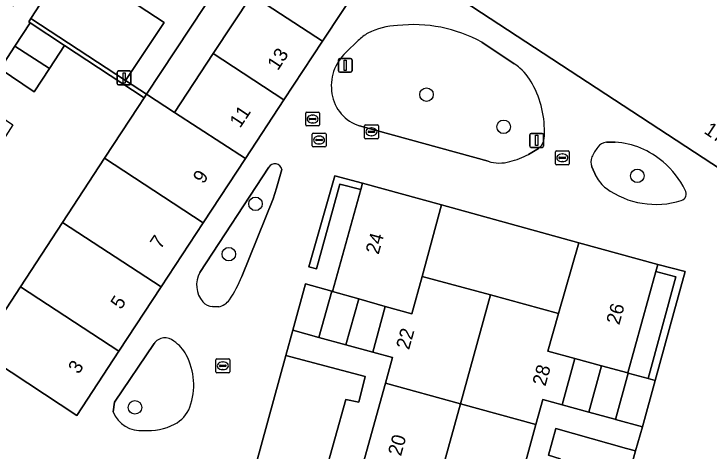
# Model space of a CAD drawing. Extents: x 159279 to 160377, y 384531 to 385888.
# Drawn here: x 159687.1 to 159737.3, y 385007.8 to 385039.4 of the extents above; entities that cross this region are included whole.
import ezdxf

# ---------------------------------------------------------------- set-up
doc = ezdxf.new("R2010")
doc.units = 0
for name, color, linetype in [('IMGEO_Boom', 7, 'Continuous'), ('IMGEO_Erf', 7, 'Continuous'), ('IMGEO_Groenvoorziening', 7, 'Continuous'), ('IMGEO_Hek', 7, 'Continuous'), ('IMGEO_Kolk', 7, 'Continuous'), ('IMGEO_Lichtmast', 7, 'Continuous'), ('IMGEO_Pand', 7, 'Continuous'), ('IMGEO_Pand_nummerreeks', 7, 'Continuous'), ('IMGEO_Parkeervlak_open', 7, 'Continuous'), ('IMGEO_Rijbaan_lokaal_open', 7, 'Continuous'), ('IMGEO_Rioolput', 7, 'Continuous'), ('IMGEO_Voetpad_open', 7, 'Continuous')]:
    doc.layers.add(name, color=color, linetype=linetype)

msp = doc.modelspace()

# ---------------------------------------------------------------- linework, layer by layer
at = {"layer": 'IMGEO_Boom'}
for centre in [(159716.879, 385033.612), (159722.449, 385031.285), (159732.109, 385027.742), (159704.53, 385025.718), (159702.603, 385022.074), (159695.825, 385011.001)]:
    msp.add_circle(centre, 0.489, dxfattribs=at)
at = {"layer": 'IMGEO_Erf'}
for points in [[(159707.037, 385045.044), (159705.037, 385046.345), (159696.664, 385033.634), (159698.671, 385032.329), (159701.473, 385036.588), (159704.263, 385040.828)], [(159693.635, 385029.02), (159696.07, 385032.741), (159696.49, 385033.372), (159690.738, 385037.169), (159689.648, 385035.49), (159688.557, 385033.812), (159686.092, 385035.477), (159684.54, 385033.097), (159687.007, 385031.43), (159685.921, 385029.756), (159684.836, 385028.082), (159683.75, 385026.408), (159681.278, 385028.08), (159679.412, 385025.221), (159681.889, 385023.564), (159680.81, 385021.913), (159679.708, 385020.226), (159677.219, 385021.881), (159676.297, 385020.469), (159684.516, 385015.086), (159687.554, 385019.728), (159690.594, 385024.374)]]:
    msp.add_lwpolyline(points, close=True, dxfattribs=at)
at = {"layer": 'IMGEO_Groenvoorziening'}
for points in [[(159688.313, 385039.115), (159688.159, 385038.87), (159688.265, 385038.797), (159690.738, 385037.169), (159696.49, 385033.372), (159696.664, 385033.634), (159695.151, 385034.636)], [(159712.135, 385026.744), (159712.264, 385027.21), (159710.255, 385027.738), (159708.395, 385021.161), (159708.936, 385021.015), (159710.631, 385027.136)], [(159727.877, 385022.906), (159717.977, 385025.649), (159716.563, 385020.475), (159721.493, 385019.127), (159726.423, 385017.779)], [(159733.579, 385021.34), (159733.438, 385020.828), (159734.885, 385020.437), (159732.892, 385013.082), (159733.39, 385012.945), (159734.748, 385017.863), (159735.566, 385020.832)], [(159706.728, 385014.756), (159702.407, 384999.024), (159702.463, 384999.012), (159702.875, 384998.904), (159707.309, 384997.745), (159708.147, 384997.525), (159708.628, 384999.364), (159707.709, 384999.604), (159709.052, 385004.403), (159709.273, 385005.211), (159711.651, 385004.56), (159711.749, 385004.916), (159711.833, 385005.22), (159709.458, 385005.886), (159711.051, 385011.567), (159711.984, 385011.373), (159712.446, 385013.228)], [(159731.988, 385007.852), (159731.335, 385008.036), (159726.225, 385009.479), (159725.699, 385007.547), (159726.546, 385007.283), (159725.336, 385002.644), (159725.001, 385001.456), (159722.677, 385002.088), (159722.628, 385001.911), (159722.576, 385001.723), (159724.905, 385001.064), (159723.474, 384995.85), (159723.308, 384995.283), (159723.108, 384995.336), (159722.416, 384995.519), (159721.904, 384993.59), (159727.401, 384992.085), (159727.639, 384992.018)]]:
    msp.add_lwpolyline(points, close=True, dxfattribs=at)
for points in [[(159711.955, 385037.529), (159711.051, 385036.645)], [(159723.208, 385035.834), (159720.868, 385037.407)], [(159712.052, 385031.348), (159721.336, 385028.789)], [(159730.511, 385030.176), (159729.874, 385030.174)], [(159724.255, 385029.29), (159724.964, 385029.723)], [(159705.5, 385028.368), (159700.508, 385020.752)], [(159703.552, 385020.471), (159705.815, 385026.087), (159706.06, 385026.856), (159706.426, 385028.202)], [(159728.831, 385028.381), (159729.145, 385027.684)], [(159701.418, 385018.285), (159701.872, 385018.268)], [(159697.203, 385015.616), (159694.341, 385011.373)], [(159694.341, 385011.373), (159694.249, 385010.673)]]:
    msp.add_lwpolyline(points, dxfattribs=at)
for centre, radius, start, end in [((159714.985, 385033.449), 5.158, 92.2605, 116.8738), ((159715.929, 385028.357), 10.31, 61.3761, 96.3881), ((159714.44, 385034.924), 3.6, 119.7448, 133.6533), ((159713.279, 385034.246), 3.274, 132.8813, 190.1333), ((159722.59, 385034.575), 1.402, 42.2413, 63.8445), ((159720.925, 385032.429), 4.104, 25.0343, 48.8139), ((159718.388, 385030.997), 7.013, 355.266, 26.8654), ((159712.908, 385034.102), 2.884, 188.6226, 252.7424), ((159724.394, 385030.532), 0.99, 305.1831, 353.3756), ((159730.003, 385029.233), 0.95, 97.7841, 142.8195), ((159730.134, 385024.353), 5.835, 48.8814, 86.2934), ((159732.099, 385027.644), 3.581, 142.8282, 155.964), ((159721.487, 385034.535), 5.93, 283.7329, 297.8218), ((159729.601, 385028.744), 0.851, 155.0924, 205.2254), ((159705.931, 385028.108), 0.504, 10.7746, 148.8989), ((159722.14, 385031.339), 2.674, 252.4994, 286.3981), ((159729.814, 385023.859), 6.418, 26.3701, 49.6285), ((159731.395, 385028.857), 2.538, 207.5406, 232.5773), ((159733.448, 385031.782), 6.109, 233.9526, 287.4686), ((159735.133, 385026.44), 0.509, 287.0404, 32.0469), ((159702.14, 385019.85), 1.864, 151.0731, 220.6856), ((159694.881, 385024.007), 9.364, 326.0617, 337.8144), ((159701.496, 385019.298), 1.016, 220.7307, 265.6105), ((159701.579, 385019.562), 1.327, 282.7638, 323.831), ((159697.995, 385015.066), 0.965, 48.0475, 145.2102), ((159697.307, 385013.7), 2.473, 26.2591, 57.388), ((159695.403, 385012.606), 4.666, 340.1761, 27.9563), ((159697.664, 385011.827), 2.275, 296.6333, 339.3357), ((159696.242, 385011.479), 2.149, 202.0248, 275.6203), ((159696.817, 385013.267), 3.944, 264.6911, 298.2544)]:
    msp.add_arc(centre, radius, start, end, dxfattribs=at)
at = {"layer": 'IMGEO_Hek'}
msp.add_lwpolyline([(159707.037, 385045.044), (159705.037, 385046.345), (159696.664, 385033.634)], dxfattribs=at)
at = {"layer": 'IMGEO_Kolk'}
for p, q in [((159712.406, 385030.493), (159712.406, 385031.345)), ((159712.481, 385031.419), (159713.333, 385031.419)), ((159712.894, 385031.199), (159712.919, 385031.199)), ((159713.407, 385031.345), (159713.407, 385030.493)), ((159712.665, 385030.913), (159712.665, 385030.925)), ((159713.103, 385030.876), (159712.705, 385030.876)), ((159712.708, 385030.962), (159713.106, 385030.962)), ((159712.917, 385030.639), (159712.892, 385030.639)), ((159713.149, 385030.925), (159713.149, 385030.913)), ((159713.333, 385030.419), (159712.481, 385030.419)), ((159726.189, 385028.618), (159726.189, 385029.47)), ((159726.264, 385029.544), (159727.116, 385029.544)), ((159726.448, 385029.038), (159726.448, 385029.05)), ((159726.491, 385029.087), (159726.889, 385029.087)), ((159726.677, 385029.324), (159726.702, 385029.324)), ((159726.932, 385029.05), (159726.932, 385029.038)), ((159727.19, 385029.47), (159727.19, 385028.618)), ((159726.886, 385029.001), (159726.488, 385029.001)), ((159726.7, 385028.764), (159726.675, 385028.764)), ((159727.116, 385028.544), (159726.264, 385028.544)), ((159701.747, 385014.51), (159702.599, 385014.51)), ((159701.672, 385013.584), (159701.672, 385014.436)), ((159701.931, 385014.004), (159701.931, 385014.016)), ((159701.974, 385014.053), (159702.372, 385014.053)), ((159702.16, 385014.29), (159702.185, 385014.29)), ((159702.415, 385014.016), (159702.415, 385014.004)), ((159702.673, 385014.436), (159702.673, 385013.584)), ((159702.599, 385013.51), (159701.747, 385013.51)), ((159702.369, 385013.967), (159701.971, 385013.967)), ((159702.183, 385013.73), (159702.158, 385013.73))]:
    msp.add_line(p, q, dxfattribs=at)
for points in [[(159712.406, 385030.493), (159712.406, 385031.345)], [(159712.481, 385031.419), (159713.333, 385031.419)], [(159713.407, 385031.345), (159713.407, 385030.493)], [(159713.333, 385030.419), (159712.481, 385030.419)], [(159726.189, 385028.618), (159726.189, 385029.47)], [(159726.264, 385029.544), (159727.116, 385029.544)], [(159727.19, 385029.47), (159727.19, 385028.618)], [(159727.116, 385028.544), (159726.264, 385028.544)], [(159701.747, 385014.51), (159702.599, 385014.51)], [(159701.672, 385013.584), (159701.672, 385014.436)], [(159702.673, 385014.436), (159702.673, 385013.584)], [(159702.599, 385013.51), (159701.747, 385013.51)]]:
    msp.add_lwpolyline(points, dxfattribs=at)
for centre, radius, start, end in [((159712.483, 385031.343), 0.0765, 91.552, 178.448), ((159712.483, 385031.343), 0.0765, 91.552, 178.448), ((159713.331, 385031.343), 0.0765, 1.552, 88.448), ((159713.331, 385031.343), 0.0765, 1.552, 88.448), ((159712.705, 385030.922), 0.0403, 85.8775, 175.7526), ((159712.702, 385030.912), 0.0366, 178.938, 274.7102), ((159713.106, 385030.919), 0.043, 264.8664, 352.4533), ((159713.11, 385030.924), 0.0386, 1.7309, 96.639), ((159712.483, 385030.495), 0.0765, 181.552, 268.448), ((159712.483, 385030.495), 0.0765, 181.552, 268.448), ((159713.331, 385030.495), 0.0765, 271.552, 358.448), ((159713.331, 385030.495), 0.0765, 271.552, 358.448), ((159726.266, 385029.468), 0.0765, 91.552, 178.448), ((159726.266, 385029.468), 0.0765, 91.552, 178.448), ((159726.488, 385029.047), 0.0403, 85.8775, 175.7526), ((159726.893, 385029.049), 0.0386, 1.7309, 96.639), ((159727.114, 385029.468), 0.0765, 1.552, 88.448), ((159727.114, 385029.468), 0.0765, 1.552, 88.448), ((159726.266, 385028.62), 0.0765, 181.552, 268.448), ((159726.266, 385028.62), 0.0765, 181.552, 268.448), ((159726.485, 385029.037), 0.0366, 178.938, 274.7102), ((159726.889, 385029.044), 0.043, 264.8664, 352.4533), ((159727.114, 385028.62), 0.0765, 271.552, 358.448), ((159727.114, 385028.62), 0.0765, 271.552, 358.448), ((159701.749, 385014.434), 0.0765, 91.552, 178.448), ((159701.749, 385014.434), 0.0765, 91.552, 178.448), ((159702.597, 385014.434), 0.0765, 1.552, 88.448), ((159702.597, 385014.434), 0.0765, 1.552, 88.448), ((159701.971, 385014.013), 0.0403, 85.8775, 175.7526), ((159701.968, 385014.003), 0.0366, 178.938, 274.7102), ((159702.372, 385014.01), 0.043, 264.8664, 352.4533), ((159702.376, 385014.015), 0.0386, 1.7309, 96.639), ((159701.749, 385013.586), 0.0765, 181.552, 268.448), ((159701.749, 385013.586), 0.0765, 181.552, 268.448), ((159702.597, 385013.586), 0.0765, 271.552, 358.448), ((159702.597, 385013.586), 0.0765, 271.552, 358.448)]:
    msp.add_arc(centre, radius, start, end, dxfattribs=at)
for centre, major_axis, ratio, start_param, end_param in [((159712.893, 385030.919), (-0.387, 0.002), 0.722429, 4.712389, 7.853982), ((159712.918, 385030.919), (-0.39, 0.002), 0.717154, 1.570796, 4.712389), ((159726.676, 385029.044), (-0.387, 0.002), 0.722429, 4.712389, 7.853982), ((159726.701, 385029.044), (-0.39, 0.002), 0.717154, 1.570796, 4.712389), ((159702.159, 385014.01), (-0.387, 0.002), 0.722429, 4.712389, 7.853982), ((159702.184, 385014.01), (-0.39, 0.002), 0.717154, 1.570796, 4.712389)]:
    msp.add_ellipse(centre, major_axis=major_axis, ratio=ratio, start_param=start_param, end_param=end_param, dxfattribs=at)
at = {"layer": 'IMGEO_Lichtmast'}
for p, q in [((159710.515, 385035.324), (159710.515, 385036.124)), ((159710.515, 385036.124), (159710.515, 385035.324)), ((159710.615, 385036.224), (159711.405, 385036.224)), ((159711.405, 385036.224), (159710.615, 385036.224)), ((159711.505, 385036.124), (159711.505, 385035.324)), ((159711.505, 385035.324), (159711.505, 385036.124)), ((159694.547, 385034.417), (159694.547, 385035.217)), ((159694.547, 385035.217), (159694.547, 385034.417)), ((159694.647, 385035.317), (159695.437, 385035.317)), ((159695.437, 385035.317), (159694.647, 385035.317)), ((159695.537, 385035.217), (159695.537, 385034.417)), ((159695.537, 385034.417), (159695.537, 385035.217)), ((159711.405, 385035.224), (159710.615, 385035.224)), ((159710.615, 385035.224), (159711.405, 385035.224)), ((159695.437, 385034.317), (159694.647, 385034.317)), ((159694.647, 385034.317), (159695.437, 385034.317)), ((159724.346, 385029.895), (159724.346, 385030.695)), ((159724.346, 385030.695), (159724.346, 385029.895)), ((159724.446, 385030.795), (159725.236, 385030.795)), ((159725.236, 385030.795), (159724.446, 385030.795)), ((159725.336, 385030.695), (159725.336, 385029.895)), ((159725.336, 385029.895), (159725.336, 385030.695)), ((159725.236, 385029.795), (159724.446, 385029.795)), ((159724.446, 385029.795), (159725.236, 385029.795))]:
    msp.add_line(p, q, dxfattribs=at)
for points in [[(159710.935, 385036.099), (159711.085, 385036.099), (159711.085, 385035.349), (159710.935, 385035.349), (159710.935, 385036.099)], [(159694.967, 385035.192), (159695.117, 385035.192), (159695.117, 385034.442), (159694.967, 385034.442), (159694.967, 385035.192)], [(159724.766, 385030.67), (159724.916, 385030.67), (159724.916, 385029.92), (159724.766, 385029.92), (159724.766, 385030.67)]]:
    msp.add_lwpolyline(points, dxfattribs=at)
for centre, start, end in [((159710.615, 385036.124), 90, 180), ((159710.615, 385036.124), 90, 180), ((159711.405, 385036.124), 0, 90), ((159711.405, 385036.124), 360, 90), ((159694.647, 385035.217), 90, 180), ((159694.647, 385035.217), 90, 180), ((159695.437, 385035.217), 0, 90), ((159695.437, 385035.217), 360, 90), ((159710.615, 385035.324), 180, 270), ((159710.615, 385035.324), 180, 270), ((159711.405, 385035.324), 270, 0), ((159711.405, 385035.324), 270, 0), ((159694.647, 385034.417), 180, 270), ((159694.647, 385034.417), 180, 270), ((159695.437, 385034.417), 270, 0), ((159695.437, 385034.417), 270, 0), ((159724.446, 385030.695), 90, 180), ((159724.446, 385030.695), 90, 180), ((159725.236, 385030.695), 0, 90), ((159725.236, 385030.695), 360, 90), ((159724.446, 385029.895), 180, 270), ((159724.446, 385029.895), 180, 270), ((159725.236, 385029.895), 270, 0), ((159725.236, 385029.895), 270, 0)]:
    msp.add_arc(centre, 0.1, start, end, dxfattribs=at)
at = {"layer": 'IMGEO_Pand'}
for points in [[(159721.603, 385051.823), (159715.693, 385042.917), (159752.249, 385018.976), (159756.551, 385025.584), (159756.906, 385026.112), (159757.162, 385026.161), (159758.452, 385026.409), (159758.603, 385026.313), (159759.18, 385027.212)], [(159707.037, 385045.044), (159704.263, 385040.828), (159709.37, 385037.48), (159712.153, 385041.724), (159707.783, 385044.559)], [(159704.263, 385040.828), (159701.473, 385036.588), (159706.587, 385033.235), (159709.37, 385037.48)], [(159688.265, 385038.797), (159687.159, 385037.107), (159689.648, 385035.49), (159690.738, 385037.169)], [(159687.159, 385037.107), (159686.092, 385035.477), (159688.557, 385033.812), (159689.648, 385035.49)], [(159701.473, 385036.588), (159698.671, 385032.329), (159703.805, 385028.991), (159706.587, 385033.235)], [(159698.671, 385032.329), (159696.664, 385033.634), (159696.49, 385033.372), (159696.07, 385032.741), (159693.635, 385029.02), (159700.76, 385024.348), (159703.805, 385028.991)], [(159693.635, 385029.02), (159690.594, 385024.374), (159697.716, 385019.705), (159700.76, 385024.348)], [(159717.977, 385025.649), (159712.264, 385027.21), (159712.135, 385026.744), (159710.099, 385019.376), (159711.983, 385018.844), (159713.908, 385018.301), (159715.821, 385017.76), (159716.563, 385020.475)], [(159690.594, 385024.374), (159687.554, 385019.728), (159694.671, 385015.061), (159697.716, 385019.705)], [(159733.438, 385020.828), (159733.579, 385021.34), (159727.877, 385022.906), (159726.423, 385017.779), (159725.655, 385015.073), (159727.589, 385014.541), (159729.523, 385014.009), (159731.416, 385013.488)], [(159721.493, 385019.127), (159716.563, 385020.475), (159715.821, 385017.76), (159713.908, 385018.301), (159712.995, 385014.998), (159714.424, 385014.606), (159713.915, 385012.762), (159719.329, 385011.266)], [(159687.554, 385019.728), (159684.516, 385015.086), (159691.627, 385010.418), (159694.671, 385015.061)], [(159710.037, 385019.393), (159708.144, 385019.928), (159707.23, 385016.582), (159709.117, 385016.064)], [(159711.983, 385018.844), (159710.099, 385019.376), (159710.037, 385019.393), (159709.117, 385016.064), (159711.067, 385015.528)], [(159727.589, 385014.541), (159725.655, 385015.073), (159726.423, 385017.779), (159721.493, 385019.127), (159719.329, 385011.266), (159724.784, 385009.759), (159725.283, 385011.575), (159726.669, 385011.194)], [(159713.908, 385018.301), (159711.983, 385018.844), (159711.067, 385015.528), (159712.995, 385014.998)], [(159729.523, 385014.009), (159727.589, 385014.541), (159726.669, 385011.194), (159728.602, 385010.663)], [(159731.456, 385013.477), (159731.416, 385013.488), (159729.523, 385014.009), (159728.602, 385010.663), (159730.495, 385010.143), (159730.536, 385010.132)], [(159733.39, 385012.945), (159732.892, 385013.082), (159731.456, 385013.477), (159730.536, 385010.132), (159732.476, 385009.599)], [(159719.329, 385011.266), (159713.915, 385012.762), (159711.833, 385005.22), (159711.749, 385004.916), (159717.169, 385003.419)], [(159724.784, 385009.759), (159719.329, 385011.266), (159717.169, 385003.419), (159722.628, 385001.911), (159722.677, 385002.088)]]:
    msp.add_lwpolyline(points, close=True, dxfattribs=at)
at = {"layer": 'IMGEO_Parkeervlak_open'}
msp.add_lwpolyline([(159691.051, 385043.344), (159688.313, 385039.115), (159695.151, 385034.636), (159697.947, 385038.822)], close=True, dxfattribs=at)
at = {"layer": 'IMGEO_Rijbaan_lokaal_open'}
for points in [[(159752.249, 385018.976), (159715.693, 385042.917), (159713.684, 385044.233), (159713.132, 385044.595), (159714.557, 385046.77), (159711.001, 385049.098), (159709.793, 385047.246), (159709.583, 385046.927), (159709.408, 385047.042), (159690.113, 385059.669), (159688.052, 385061.026), (159684.69, 385055.888)], [(159681.638, 385049.533), (159689.734, 385044.198), (159691.051, 385043.344), (159697.947, 385038.822), (159695.151, 385034.636), (159696.664, 385033.634), (159705.037, 385046.345), (159707.037, 385045.044), (159707.783, 385044.559), (159712.153, 385041.724), (159709.37, 385037.48), (159706.587, 385033.235), (159703.805, 385028.991), (159700.76, 385024.348), (159697.716, 385019.705), (159694.671, 385015.061), (159691.627, 385010.418), (159684.516, 385015.086)], [(159711.051, 385036.645), (159711.955, 385037.529)], [(159720.868, 385037.407), (159723.208, 385035.834)], [(159721.336, 385028.789), (159712.052, 385031.348)], [(159729.874, 385030.174), (159730.511, 385030.176)], [(159724.964, 385029.723), (159724.255, 385029.29)], [(159700.508, 385020.752), (159705.5, 385028.368)], [(159706.426, 385028.202), (159706.06, 385026.856), (159705.815, 385026.087), (159703.552, 385020.471)], [(159729.145, 385027.684), (159728.831, 385028.381)], [(159702.407, 384999.024), (159706.728, 385014.756), (159707.23, 385016.582), (159708.144, 385019.928), (159710.037, 385019.393), (159710.099, 385019.376), (159712.135, 385026.744), (159710.631, 385027.136), (159708.936, 385021.015), (159708.395, 385021.161), (159710.255, 385027.738), (159712.264, 385027.21), (159717.977, 385025.649), (159727.877, 385022.906), (159733.579, 385021.34), (159735.566, 385020.832), (159734.748, 385017.863), (159733.39, 385012.945), (159732.476, 385009.599), (159731.988, 385007.852), (159727.639, 384992.018)], [(159701.872, 385018.268), (159701.418, 385018.285)], [(159694.249, 385010.673), (159694.341, 385011.373), (159697.203, 385015.616)]]:
    msp.add_lwpolyline(points, dxfattribs=at)
for centre, radius, start, end in [((159714.985, 385033.449), 5.158, 92.2605, 116.8738), ((159715.929, 385028.357), 10.31, 61.3761, 96.3881), ((159714.44, 385034.924), 3.6, 119.7448, 133.6533), ((159713.279, 385034.246), 3.274, 132.8813, 190.1333), ((159722.59, 385034.575), 1.402, 42.2413, 63.8445), ((159720.925, 385032.429), 4.104, 25.0343, 48.8139), ((159718.388, 385030.997), 7.013, 355.266, 26.8654), ((159712.908, 385034.102), 2.884, 188.6226, 252.7424), ((159724.394, 385030.532), 0.99, 305.1831, 353.3756), ((159730.003, 385029.233), 0.95, 97.7841, 142.8195), ((159730.134, 385024.353), 5.835, 48.8814, 86.2934), ((159732.099, 385027.644), 3.581, 142.8282, 155.964), ((159721.487, 385034.535), 5.93, 283.7329, 297.8218), ((159729.601, 385028.744), 0.851, 155.0924, 205.2254), ((159705.931, 385028.108), 0.504, 10.7746, 148.8989), ((159722.14, 385031.339), 2.674, 252.4994, 286.3981), ((159729.814, 385023.859), 6.418, 26.3701, 49.6285), ((159731.395, 385028.857), 2.538, 207.5406, 232.5773), ((159733.448, 385031.782), 6.109, 233.9526, 287.4686), ((159735.133, 385026.44), 0.509, 287.0404, 32.0469), ((159702.14, 385019.85), 1.864, 151.0731, 220.6856), ((159694.881, 385024.007), 9.364, 326.0617, 337.8144), ((159701.496, 385019.298), 1.016, 220.7307, 265.6105), ((159701.579, 385019.562), 1.327, 282.7638, 323.831), ((159697.995, 385015.066), 0.965, 48.0475, 145.2102), ((159697.307, 385013.7), 2.473, 26.2591, 57.388), ((159695.403, 385012.606), 4.666, 340.1761, 27.9563), ((159697.664, 385011.827), 2.275, 296.6333, 339.3357), ((159696.242, 385011.479), 2.149, 202.0248, 275.6203), ((159696.817, 385013.267), 3.944, 264.6911, 298.2544)]:
    msp.add_arc(centre, radius, start, end, dxfattribs=at)
at = {"layer": 'IMGEO_Rioolput'}
for p, q in [((159708.156, 385031.418), (159708.156, 385032.27)), ((159708.231, 385032.344), (159709.083, 385032.344)), ((159708.644, 385032.124), (159708.669, 385032.124)), ((159709.157, 385032.27), (159709.157, 385031.418)), ((159708.415, 385031.838), (159708.415, 385031.85)), ((159708.853, 385031.801), (159708.455, 385031.801)), ((159708.458, 385031.887), (159708.856, 385031.887)), ((159708.667, 385031.564), (159708.642, 385031.564)), ((159708.899, 385031.85), (159708.899, 385031.838)), ((159709.083, 385031.344), (159708.231, 385031.344)), ((159708.624, 385029.9), (159708.624, 385030.752)), ((159708.699, 385030.826), (159709.551, 385030.826)), ((159709.112, 385030.606), (159709.137, 385030.606)), ((159709.625, 385030.752), (159709.625, 385029.9)), ((159708.883, 385030.32), (159708.883, 385030.332)), ((159709.321, 385030.283), (159708.923, 385030.283)), ((159708.926, 385030.369), (159709.324, 385030.369)), ((159709.367, 385030.332), (159709.367, 385030.32)), ((159709.551, 385029.826), (159708.699, 385029.826)), ((159709.135, 385030.046), (159709.11, 385030.046))]:
    msp.add_line(p, q, dxfattribs=at)
for points in [[(159708.156, 385031.418), (159708.156, 385032.27)], [(159708.231, 385032.344), (159709.083, 385032.344)], [(159709.157, 385032.27), (159709.157, 385031.418)], [(159709.083, 385031.344), (159708.231, 385031.344)], [(159708.624, 385029.9), (159708.624, 385030.752)], [(159708.699, 385030.826), (159709.551, 385030.826)], [(159709.625, 385030.752), (159709.625, 385029.9)], [(159709.551, 385029.826), (159708.699, 385029.826)]]:
    msp.add_lwpolyline(points, dxfattribs=at)
for centre, radius, start, end in [((159708.233, 385032.268), 0.0765, 91.552, 178.448), ((159708.233, 385032.268), 0.0765, 91.552, 178.448), ((159709.081, 385032.268), 0.0765, 1.552, 88.448), ((159709.081, 385032.268), 0.0765, 1.552, 88.448), ((159708.455, 385031.847), 0.0403, 85.8775, 175.7526), ((159708.452, 385031.837), 0.0366, 178.938, 274.7102), ((159708.856, 385031.844), 0.043, 264.8664, 352.4533), ((159708.86, 385031.849), 0.0386, 1.7309, 96.639), ((159708.233, 385031.42), 0.0765, 181.552, 268.448), ((159708.233, 385031.42), 0.0765, 181.552, 268.448), ((159709.081, 385031.42), 0.0765, 271.552, 358.448), ((159709.081, 385031.42), 0.0765, 271.552, 358.448), ((159708.701, 385030.75), 0.0765, 91.552, 178.448), ((159708.701, 385030.75), 0.0765, 91.552, 178.448), ((159709.549, 385030.75), 0.0765, 1.552, 88.448), ((159709.549, 385030.75), 0.0765, 1.552, 88.448), ((159708.923, 385030.329), 0.0403, 85.8775, 175.7526), ((159708.92, 385030.319), 0.0366, 178.938, 274.7102), ((159709.324, 385030.326), 0.043, 264.8664, 352.4533), ((159709.328, 385030.331), 0.0386, 1.7309, 96.639), ((159708.701, 385029.902), 0.0765, 181.552, 268.448), ((159708.701, 385029.902), 0.0765, 181.552, 268.448), ((159709.549, 385029.902), 0.0765, 271.552, 358.448), ((159709.549, 385029.902), 0.0765, 271.552, 358.448)]:
    msp.add_arc(centre, radius, start, end, dxfattribs=at)
for centre, major_axis, ratio, start_param, end_param in [((159708.643, 385031.844), (-0.387, 0.002), 0.722429, 4.712389, 7.853982), ((159708.668, 385031.844), (-0.39, 0.002), 0.717154, 1.570796, 4.712389), ((159709.111, 385030.326), (-0.387, 0.002), 0.722429, 4.712389, 7.853982), ((159709.136, 385030.326), (-0.39, 0.002), 0.717154, 1.570796, 4.712389)]:
    msp.add_ellipse(centre, major_axis=major_axis, ratio=ratio, start_param=start_param, end_param=end_param, dxfattribs=at)
at = {"layer": 'IMGEO_Voetpad_open'}
msp.add_lwpolyline([(159686.092, 385035.477), (159687.159, 385037.107), (159688.265, 385038.797), (159688.159, 385038.87), (159688.313, 385039.115), (159691.051, 385043.344), (159689.734, 385044.198), (159686.993, 385040.001)], dxfattribs=at)
for points in [[(159734.885, 385020.437), (159733.438, 385020.828), (159731.416, 385013.488), (159731.456, 385013.477), (159732.892, 385013.082)], [(159713.915, 385012.762), (159714.424, 385014.606), (159712.995, 385014.998), (159711.067, 385015.528), (159709.117, 385016.064), (159707.23, 385016.582), (159706.728, 385014.756), (159712.446, 385013.228), (159711.984, 385011.373), (159711.051, 385011.567), (159709.458, 385005.886), (159711.833, 385005.22)], [(159726.546, 385007.283), (159725.699, 385007.547), (159726.225, 385009.479), (159731.335, 385008.036), (159731.988, 385007.852), (159732.476, 385009.599), (159730.536, 385010.132), (159730.495, 385010.143), (159728.602, 385010.663), (159726.669, 385011.194), (159725.283, 385011.575), (159724.784, 385009.759), (159722.677, 385002.088), (159725.001, 385001.456), (159725.336, 385002.644)]]:
    msp.add_lwpolyline(points, close=True, dxfattribs=at)

# ---------------------------------------------------------------- texts
at = {"layer": 'IMGEO_Pand_nummerreeks'}
for s, rotation, p in [('13', 56.5509, (159706.145, 385035.301)), ('11', 56.5509, (159703.419, 385031.143)), ('17-25', 326.5794, (159736.856, 385030.86)), ('9', 56.5509, (159700.772, 385027.104)), ('24', 74.3527, (159713.418, 385022.009)), ('7', 56.5509, (159697.679, 385022.386)), ('5', 56.5509, (159694.819, 385018.025)), ('26', 74.3986, (159730.802, 385016.92)), ('22', 74.3527, (159715.62, 385015.12)), ('3', 56.5509, (159691.757, 385013.354)), ('28', 74.4215, (159725.465, 385012.484)), ('20', 74.3699, (159715.034, 385007.431))]:
    msp.add_text(s, height=1, rotation=rotation, dxfattribs=at).set_placement(p)

doc.saveas('drawing.dxf')
